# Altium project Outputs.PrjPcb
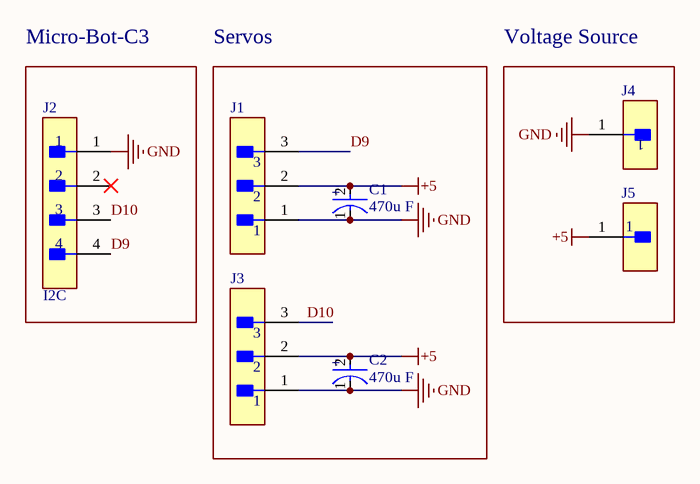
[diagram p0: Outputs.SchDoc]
1 sheet, 7 parts. Net scope: global (net labels, ports and power ports of the same name join across sheets).
Board file: Outputs.PcbDoc

## Sheet Outputs.SchDoc
size A4; SheetNumber: 1; SheetTotal: 1

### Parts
C1  470u F  [FP-RAD-TH-D_12_5_0_5-L_25-MFG]
C2  470u F  [FP-RAD-TH-D_12_5_0_5-L_25-MFG]
J1  (no value)  [FP-22-28-4030-MFG]
J2  I2C  [FP-TSW-104-23-T-S-MFG]
J3  (no value)  [FP-22-28-4030-MFG]
J4  (no value)  [FP-HTSW-101-07-L-S-MFG]
J5  (no value)  [FP-HTSW-101-07-L-S-MFG]

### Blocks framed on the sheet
Micro-Bot-C3: J2
Servos: C1 C2 J1 J3
Voltage Source: J4 J5

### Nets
+5: C1.2(A) C2.2(A) J1.2 J3.2 J5.1
GND: C1.1(C) C2.1(C) J1.1 J2.1 J3.1 J4.1
D9: J1.3 J2.4
D10: J2.3 J3.3

Not connected (* = marked no-connect by the designer): J2 2*

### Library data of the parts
C1 C2 = CMP-05427-000674-1: Aluminum Electrolytic Capacitors (Radial Lead Type) AEC-Q200 Qualified 470uF ±20% 50V; Ripple Current: 1.832A; Leakage Current: 3uA; Impedance: 50mR; Lead Diameter: 0.6mm; Dielectric Material: Aluminium; Polarity: Polar; Life (Hours): 5000Hour
J1 J3 = CMP-04776-000098-1: CONN HEADER VERT 3POS 2.54MM; Manufacturer: Molex; Conn Orientation: Vertical; Conn Gender: Male; Current Rating: 4A; Voltage Rating: 500V; Number Of Contacts: 3
J2 = CMP-02766-001388-1: CONN HEADER VERT 4POS 2.54MM; Number of Contacts: 4; Gender: Male; Connector Type: Male Pin; Max Voltage Rating (AC): 550V; Max Current Rating: 7.6A
J4 J5 = CMP-02766-001464-1: CONN HEADER VERT 1POS; Number of Contacts: 1; Max Voltage Rating (AC): 550V; Gender: Male; Max Current Rating: 7.6A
